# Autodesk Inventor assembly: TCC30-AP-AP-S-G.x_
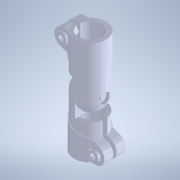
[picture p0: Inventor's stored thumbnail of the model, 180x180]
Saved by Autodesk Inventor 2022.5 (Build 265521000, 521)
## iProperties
Created: 2023-09
Part Number: TCC30-AP-AP-S-G.x_
Document SubType Name: Assembly
Designer: ImaoCorp
Sending System: SOLIDWORKS 2021-2021301
MC: AMD64
MC_MODEL: Intel64 Family 6 Model 60 Stepping 3, GenuineIntel
OS: Windows_NT
FRU: Parasolid Version 32.1, build 255,  1- 1-2021
FORMAT: text
GUISE: transmit
KEY: TCC30-AP-AP-S-G
FILE: TCC30-AP-AP-S-G.x_t
DATE: Fri Sep 15 15:35:22 2023
Author: ImaoCorp
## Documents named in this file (9)
- X:\14_SW2022-Inv2022\00_全2023-1023新製品(TCC)まで\t\tcc30-ap-ap-s-g\TCC30-AP-AP-S-G.iam
- X:\14_SW2022-Inv2022\00_全2023-1023新製品(TCC)まで\t\tcc30-ap-ap-s-g\TCC30-AP-AP-S-G_01.ipt
- X:\14_SW2022-Inv2022\00_全2023-1023新製品(TCC)まで\t\tcc30-ap-ap-s-g\TCC30-AP-AP-S-G_02.ipt
- X:\14_SW2022-Inv2022\00_全2023-1023新製品(TCC)まで\t\tcc30-ap-ap-s-g\TCC30-AP-AP-S-G_03.ipt
- X:\14_SW2022-Inv2022\00_全2023-1023新製品(TCC)まで\t\tcc30-ap-ap-s-g\TCC30-AP-AP-S-G_04.ipt
- X:\14_SW2022-Inv2022\00_全2023-1023新製品(TCC)まで\t\tcc30-ap-ap-s-g\TCC30-AP-AP-S-G_05.ipt
- X:\14_SW2022-Inv2022\00_全2023-1023新製品(TCC)まで\t\tcc30-ap-ap-s-g\TCC30-AP-AP-S-G_06.ipt
- X:\14_SW2022-Inv2022\00_全2023-1023新製品(TCC)まで\t\tcc30-ap-ap-s-g\TCC30-AP-AP-S-G_07.ipt
- X:\14_SW2022-Inv2022\00_全2023-1023新製品(TCC)まで\t\tcc30-ap-ap-s-g\TCC30-AP-AP-S-G_08.ipt
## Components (8 placed, 8 different names)
1. TCC30-AP-AP-S-G_01
2. TCC30-AP-AP-S-G_02
3. TCC30-AP-AP-S-G_03
4. TCC30-AP-AP-S-G_04
5. TCC30-AP-AP-S-G_05
6. TCC30-AP-AP-S-G_06
7. TCC30-AP-AP-S-G_07
8. TCC30-AP-AP-S-G_08
